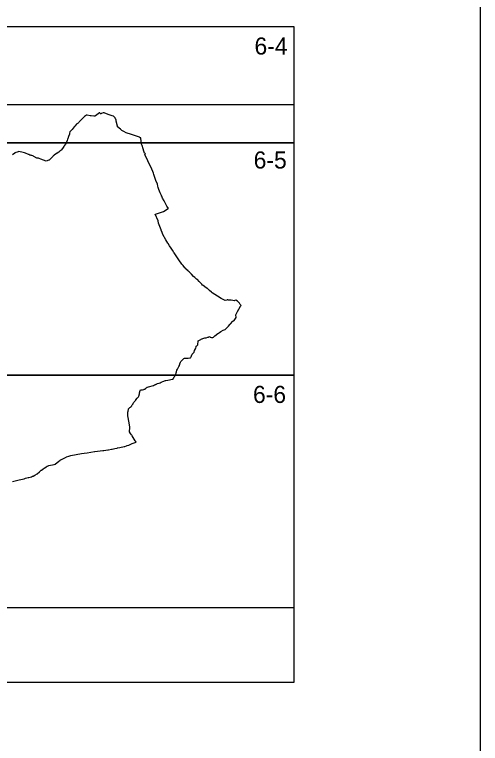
# Model space of a CAD drawing. Extents: x -447352 to -425530, y -1135906 to -1121091.
# Drawn here: x -439936.1 to -439685.5, y -1126663.9 to -1126271.9 of the extents above; entities that cross this region are included whole.
import ezdxf

# ---------------------------------------------------------------- set-up
doc = ezdxf.new("R2010")
doc.units = 0
for name, color, linetype in [('Vrstva 1', 7, 'Continuous'), ('Vrstva 10', 7, 'Continuous'), ('Vrstva 4', 7, 'Continuous')]:
    doc.layers.add(name, color=color, linetype=linetype)

msp = doc.modelspace()

# ---------------------------------------------------------------- linework, layer by layer
at = {"layer": 'Vrstva 1'}
msp.add_lwpolyline([(-441170.45, -1126016.81), (-441170.45, -1127066.81), (-439685.45, -1127066.81), (-439685.45, -1126016.81)], close=True, dxfattribs=at)
msp.add_lwpolyline([(-439937.16, -1126523.09), (-439933.62, -1126522.22), (-439930.85, -1126521.55), (-439930.18, -1126521.34), (-439928.69, -1126520.98), (-439928.48, -1126520.92), (-439927.05, -1126520.53), (-439926.45, -1126520.27), (-439926.23, -1126520.17), (-439926.07, -1126520.11), (-439925.25, -1126519.66), (-439925.19, -1126519.62), (-439923.88, -1126518.84), (-439922.73, -1126517.79), (-439922.08, -1126517.29), (-439921.95, -1126517.18), (-439921.93, -1126517.17), (-439921.77, -1126517.04), (-439921.62, -1126516.94), (-439920.82, -1126516.38), (-439920.76, -1126516.34), (-439920.69, -1126516.29), (-439920.18, -1126515.94), (-439919.81, -1126515.68), (-439919.15, -1126515.22), (-439918.56, -1126514.81), (-439918.4, -1126514.84), (-439918.39, -1126514.84), (-439918.37, -1126514.82), (-439917.64, -1126514.43), (-439914.68, -1126513.85), (-439914.26, -1126513.7), (-439912.23, -1126512.07), (-439911.76, -1126511.73), (-439911.73, -1126511.71), (-439911.37, -1126511.45), (-439911.19, -1126511.33), (-439909.8, -1126510.63), (-439908.39, -1126509.99), (-439908.09, -1126509.84), (-439906.83, -1126509.38), (-439905.83, -1126509.13), (-439900.12, -1126508.07), (-439898.7, -1126507.81), (-439896.99, -1126507.56), (-439893.12, -1126506.99), (-439892.88, -1126506.96), (-439888.58, -1126506.44), (-439888.05, -1126506.38), (-439885.9, -1126506.02), (-439885.58, -1126505.97), (-439883.92, -1126505.7), (-439883.52, -1126505.63), (-439882.11, -1126505.34), (-439880.82, -1126505.07), (-439880.61, -1126505.03), (-439879.44, -1126504.8), (-439878.77, -1126504.67), (-439878.75, -1126504.67), (-439877.84, -1126504.46), (-439877.77, -1126504.44), (-439877.12, -1126504.28), (-439876.77, -1126504.17), (-439875.88, -1126503.88), (-439875.44, -1126503.73), (-439874.79, -1126503.49), (-439874.67, -1126503.45), (-439873.58, -1126502.96), (-439873.58, -1126502.96), (-439873.46, -1126502.92), (-439872.81, -1126502.69), (-439872.72, -1126502.66), (-439872.29, -1126502.5), (-439870.63, -1126501.92), (-439870.65, -1126501.87), (-439870.76, -1126501.7), (-439870.92, -1126501.47), (-439871.14, -1126501.15), (-439872.84, -1126498.51), (-439873.05, -1126498.16), (-439873.22, -1126497.89), (-439873.66, -1126497.18), (-439874.19, -1126496.33), (-439874.03, -1126493.97), (-439874.02, -1126493.88), (-439874.41, -1126491.58), (-439874.41, -1126491.56), (-439874.42, -1126491.54), (-439874.42, -1126491.54), (-439874.42, -1126491.51), (-439874.83, -1126489.68), (-439874.84, -1126489.49), (-439874.9, -1126488.69), (-439875, -1126488.41), (-439875.01, -1126488.39), (-439875.12, -1126488.17), (-439875.16, -1126488.09), (-439875.17, -1126487.71), (-439875.2, -1126487.01), (-439875.15, -1126486.52), (-439875.15, -1126486.5), (-439875.06, -1126485.64), (-439875.04, -1126485.53), (-439874.75, -1126483.89), (-439874.67, -1126483.81), (-439874.37, -1126483.47), (-439874.31, -1126483.4), (-439874.05, -1126483.28), (-439873.99, -1126483.22), (-439873.73, -1126483.02), (-439873.5, -1126482.84), (-439873.29, -1126482.68), (-439873.23, -1126482.64), (-439873.15, -1126482.51), (-439873.07, -1126482.39), (-439872.96, -1126482.22), (-439872.74, -1126481.89), (-439872.32, -1126481.24), (-439872.19, -1126480.99), (-439872.18, -1126480.98), (-439872.04, -1126480.69), (-439871.99, -1126480.6), (-439871.81, -1126480.27), (-439871.67, -1126480.12), (-439871.37, -1126479.81), (-439871.2, -1126479.63), (-439870.92, -1126479.28), (-439870.79, -1126479.11), (-439870.1, -1126478.26), (-439869.44, -1126477.45), (-439869.15, -1126477.09), (-439868.91, -1126475.92), (-439868.85, -1126475.69), (-439868.78, -1126475.41), (-439868.46, -1126474.1), (-439868.38, -1126473.82), (-439868.38, -1126473.79), (-439868.36, -1126473.74), (-439868.2, -1126473.73), (-439868.18, -1126473.73), (-439867.94, -1126473.73), (-439867.25, -1126473.71), (-439867.24, -1126473.71), (-439867.21, -1126473.71), (-439866.53, -1126473.53), (-439866.33, -1126473.47), (-439865.91, -1126473.36), (-439865.89, -1126473.35), (-439865.83, -1126473.29), (-439865.53, -1126473.01), (-439865.41, -1126472.93), (-439865.07, -1126472.67), (-439864.65, -1126472.35), (-439864.58, -1126472.33), (-439864.02, -1126472.17), (-439861.32, -1126471.41), (-439860.73, -1126471.14), (-439860.4, -1126470.98), (-439860.35, -1126470.96), (-439860.25, -1126470.91), (-439859.89, -1126470.73), (-439859.84, -1126470.71), (-439859.81, -1126470.69), (-439859.8, -1126470.69), (-439859.77, -1126470.67), (-439859.46, -1126470.52), (-439859.4, -1126470.48), (-439859.29, -1126470.43), (-439858.21, -1126470.1), (-439857.78, -1126469.92), (-439857.26, -1126469.7), (-439856.25, -1126469.29), (-439854.83, -1126468.66), (-439854.69, -1126468.65), (-439853.56, -1126468.6), (-439851.16, -1126468.04), (-439850.63, -1126467.64), (-439850.56, -1126467.52), (-439850.47, -1126467.34), (-439850.21, -1126466.83), (-439849.86, -1126466.4), (-439849.84, -1126466.37), (-439849.63, -1126466.08), (-439849.52, -1126465.92), (-439849.51, -1126465.91), (-439848.97, -1126464.13), (-439848.96, -1126464.1), (-439848.76, -1126463.15), (-439848.5, -1126462.69), (-439848.31, -1126462.36), (-439847.76, -1126461.24), (-439847.38, -1126460.73), (-439847.35, -1126460.6), (-439847.28, -1126460.3), (-439847.25, -1126460.16), (-439847.19, -1126459.91), (-439847.17, -1126459.81), (-439846.85, -1126458.8), (-439846.84, -1126458.79), (-439846.55, -1126458.51), (-439845.89, -1126457.88), (-439845.84, -1126457.83), (-439845.37, -1126457.35), (-439845.11, -1126457.09), (-439845.01, -1126456.98), (-439844.64, -1126456.66), (-439844.6, -1126456.66), (-439844.59, -1126456.66), (-439844.18, -1126456.65), (-439844.01, -1126456.66), (-439843.38, -1126456.68), (-439842.67, -1126456.68), (-439841.7, -1126456.59), (-439841.67, -1126456.59), (-439841.42, -1126456.56), (-439841.2, -1126456.2), (-439841.15, -1126456.07), (-439841.13, -1126456.02), (-439841.11, -1126455.96), (-439840.75, -1126454.94), (-439840.61, -1126454.77), (-439840.51, -1126454.66), (-439840.47, -1126454.62), (-439840.41, -1126454.54), (-439840.29, -1126454.41), (-439840.02, -1126454.09), (-439839.93, -1126453.99), (-439839.83, -1126453.87), (-439839.49, -1126453.48), (-439839.42, -1126453.09), (-439839.36, -1126452.78), (-439839.29, -1126452.65), (-439838.74, -1126451.73), (-439838.63, -1126451.34), (-439838.44, -1126450.64), (-439838.32, -1126450.35), (-439838.03, -1126450.08), (-439837.48, -1126449.57), (-439837.41, -1126449.51), (-439837.31, -1126447.4), (-439836.29, -1126446.91), (-439835.89, -1126446.7), (-439835.64, -1126446.57), (-439835.35, -1126446.41), (-439835.13, -1126446.33), (-439834.79, -1126446.2), (-439834.74, -1126446.19), (-439833.65, -1126445.78), (-439833.64, -1126445.78), (-439833.15, -1126445.72), (-439833.07, -1126445.7), (-439832.04, -1126445.44), (-439831.89, -1126445.4), (-439831.8, -1126445.37), (-439831.63, -1126445.32), (-439831.1, -1126445.15), (-439831.1, -1126445.15), (-439831.09, -1126445.16), (-439831.09, -1126445.16), (-439831.06, -1126445.22), (-439830.93, -1126445.44), (-439830.05, -1126445.54), (-439829.85, -1126445.56), (-439829.49, -1126445.6), (-439829.4, -1126445.56), (-439828.97, -1126445.38), (-439828.32, -1126444.67), (-439826.68, -1126443.51), (-439826.59, -1126443.44), (-439826.42, -1126443.33), (-439825.91, -1126442.91), (-439825.16, -1126442.31), (-439823.89, -1126441.74), (-439823.27, -1126441.47), (-439822.73, -1126441.23), (-439822.67, -1126441.2), (-439821.02, -1126439.53), (-439820.18, -1126438.64), (-439819.82, -1126438.26), (-439818.63, -1126436.9), (-439818.03, -1126436.44), (-439817.98, -1126436.4), (-439817.14, -1126435.39), (-439816.94, -1126434.82), (-439817.03, -1126433.49), (-439816.81, -1126433), (-439816.17, -1126431.55), (-439814.71, -1126429.07), (-439814.68, -1126429.02), (-439814.68, -1126429.02), (-439814.66, -1126428.99), (-439814.63, -1126428.95), (-439814.48, -1126428.76), (-439814.22, -1126428.42), (-439814.48, -1126428.12), (-439814.62, -1126427.9), (-439815.09, -1126427.16), (-439815.29, -1126426.97), (-439815.44, -1126426.81), (-439815.63, -1126426.61), (-439816.21, -1126426.04), (-439817.06, -1126425.57), (-439817.51, -1126425.75), (-439817.84, -1126425.87), (-439819.59, -1126425.6), (-439820.2, -1126425.51), (-439820.34, -1126425.5), (-439820.93, -1126425.48), (-439821.31, -1126425.43), (-439821.47, -1126425.4), (-439821.51, -1126425.4), (-439821.54, -1126425.39), (-439821.54, -1126425.39), (-439821.57, -1126425.4), (-439821.67, -1126425.43), (-439821.8, -1126425.46), (-439822.7, -1126425.7), (-439822.77, -1126425.67), (-439824.84, -1126424.63), (-439826.86, -1126423.35), (-439829.77, -1126421.53), (-439829.93, -1126421.39), (-439829.97, -1126421.36), (-439830.06, -1126421.28), (-439831.2, -1126420.35), (-439832.35, -1126419.3), (-439832.46, -1126419.2), (-439833.67, -1126418.44), (-439833.95, -1126418.21), (-439834.58, -1126417.71), (-439834.89, -1126417.47), (-439835.39, -1126416.94), (-439836.11, -1126416.18), (-439836.26, -1126416.02), (-439836.72, -1126415.53), (-439837.69, -1126414.5), (-439837.89, -1126414.39), (-439837.89, -1126414.39), (-439838.07, -1126414.3), (-439838.27, -1126414.2), (-439839.1, -1126413.37), (-439839.73, -1126412.74), (-439840.91, -1126411.57), (-439841.84, -1126410.63), (-439842, -1126410.48), (-439842.44, -1126410.03), (-439842.68, -1126409.79), (-439842.77, -1126409.7), (-439842.81, -1126409.66), (-439843.33, -1126409.14), (-439843.97, -1126408.49), (-439844.05, -1126408.41), (-439844.07, -1126408.39), (-439844.22, -1126408.24), (-439845.05, -1126407.4), (-439845.43, -1126406.9), (-439845.71, -1126406.53), (-439846.03, -1126406.1), (-439846.39, -1126405.62), (-439847.34, -1126404.36), (-439847.71, -1126403.82), (-439850.25, -1126400.08), (-439850.42, -1126399.82), (-439851.19, -1126398.63), (-439851.86, -1126397.62), (-439852.7, -1126396.29), (-439853.5, -1126395.02), (-439853.58, -1126394.89), (-439854.67, -1126393.04), (-439856.35, -1126390.19), (-439856.35, -1126390.18), (-439856.35, -1126390.18), (-439856.36, -1126390.18), (-439856.69, -1126389.2), (-439857.14, -1126387.9), (-439857.2, -1126387.7), (-439858.58, -1126384.19), (-439858.87, -1126382.94), (-439860.35, -1126379.26), (-439859.72, -1126379.06), (-439856, -1126377.82), (-439854.03, -1126376.6), (-439853.85, -1126376.49), (-439853.79, -1126376.45), (-439853.59, -1126376.33), (-439853.32, -1126376.16), (-439854.24, -1126374.97), (-439855.65, -1126372.19), (-439856.4, -1126370.72), (-439856.93, -1126369.56), (-439856.95, -1126369.52), (-439857.01, -1126369.39), (-439857.02, -1126369.36), (-439857.04, -1126369.33), (-439857.08, -1126369.24), (-439857.41, -1126368.51), (-439857.73, -1126367.72), (-439858.44, -1126365.95), (-439858.85, -1126364.91), (-439859, -1126364.28), (-439859.26, -1126363.15), (-439860, -1126361.26), (-439860.2, -1126360.66), (-439861.14, -1126358.03), (-439861.41, -1126357.31), (-439862.6, -1126354.22), (-439862.67, -1126354.04), (-439862.7, -1126353.96), (-439866.05, -1126347.15), (-439865.74, -1126347.01), (-439865.72, -1126347), (-439865.82, -1126346.83), (-439865.9, -1126346.73), (-439866.07, -1126346.5), (-439866.13, -1126346.42), (-439866.74, -1126344.94), (-439866.79, -1126344.65), (-439866.89, -1126344.19), (-439866.9, -1126344.13), (-439867.41, -1126342.29), (-439867.71, -1126341.66), (-439867.72, -1126341.58), (-439867.76, -1126341.22), (-439867.9, -1126340.13), (-439868.18, -1126338.29), (-439868.24, -1126338.27), (-439868.54, -1126338.17), (-439868.92, -1126337.91), (-439868.93, -1126337.91), (-439873.23, -1126336.5), (-439876.02, -1126335.52), (-439877.33, -1126334.9), (-439878.3, -1126334.34), (-439879.02, -1126333.56), (-439880.7, -1126332.29), (-439880.76, -1126331.99), (-439881.34, -1126329.29), (-439881.49, -1126328.75), (-439881.67, -1126328.24), (-439881.72, -1126328.08), (-439881.97, -1126327.56), (-439882.22, -1126327.25), (-439882.8, -1126326.56), (-439883.55, -1126326.35), (-439885.73, -1126325.69), (-439887.82, -1126324.73), (-439888.44, -1126324.73), (-439889.39, -1126325.1), (-439889.52, -1126325.19), (-439889.59, -1126325.24), (-439889.73, -1126325.34), (-439889.77, -1126325.37), (-439889.79, -1126325.35), (-439890, -1126325.1), (-439890.25, -1126324.82), (-439890.33, -1126324.72), (-439890.42, -1126324.76), (-439890.93, -1126325.15), (-439891.12, -1126325.3), (-439891.79, -1126325.82), (-439892.54, -1126326.38), (-439892.88, -1126326.6), (-439893.47, -1126326.56), (-439894.95, -1126326.41), (-439895.41, -1126326.32), (-439897, -1126326), (-439897.3, -1126326.11), (-439897.86, -1126326.46), (-439898.41, -1126326.78), (-439898.9, -1126327.24), (-439899.43, -1126327.73), (-439899.83, -1126328.12), (-439899.84, -1126328.13), (-439900.17, -1126328.47), (-439900.3, -1126328.61), (-439900.81, -1126329.16), (-439901.26, -1126329.71), (-439901.42, -1126329.9), (-439901.78, -1126330.33), (-439902.52, -1126330.66), (-439902.54, -1126330.66), (-439902.74, -1126330.91), (-439903.6, -1126331.93), (-439903.98, -1126332.38), (-439905.11, -1126333.74), (-439905.12, -1126333.75), (-439906.36, -1126334.92), (-439906.48, -1126335.76), (-439906.53, -1126336.13), (-439906.57, -1126336.23), (-439907.05, -1126337.58), (-439907.49, -1126338.82), (-439907.52, -1126338.9), (-439907.82, -1126339.59), (-439908.75, -1126341.77), (-439908.77, -1126341.78), (-439909.34, -1126342.46), (-439909.64, -1126342.81), (-439909.64, -1126342.82), (-439909.98, -1126343.36), (-439910.85, -1126344.75), (-439910.94, -1126344.89), (-439911.11, -1126345.02), (-439911.64, -1126345.41), (-439912.25, -1126345.86), (-439912.25, -1126345.86), (-439913.22, -1126346.49), (-439913.35, -1126346.58), (-439913.53, -1126346.7), (-439914.83, -1126347.56), (-439914.84, -1126347.57), (-439915.1, -1126347.83), (-439915.22, -1126347.95), (-439915.44, -1126348.18), (-439915.72, -1126348.46), (-439916.29, -1126349.03), (-439917.45, -1126350.19), (-439917.65, -1126350.27), (-439919.15, -1126350.84), (-439921.96, -1126349.72), (-439921.96, -1126349.73), (-439921.97, -1126349.75), (-439922.88, -1126349.37), (-439923.19, -1126349.24), (-439923.21, -1126349.24), (-439923.6, -1126349.24), (-439924.08, -1126349.24), (-439925.64, -1126348.25), (-439925.9, -1126348.12), (-439926.19, -1126347.96), (-439926.25, -1126347.93), (-439926.29, -1126347.91), (-439926.83, -1126347.68), (-439926.88, -1126347.68), (-439926.89, -1126347.68), (-439927.04, -1126347.67), (-439927.16, -1126347.66), (-439927.47, -1126347.64), (-439927.49, -1126347.64), (-439927.49, -1126347.64), (-439927.6, -1126347.6), (-439927.84, -1126347.5), (-439928.44, -1126347.25), (-439928.6, -1126347.18), (-439930.12, -1126346.45), (-439930.74, -1126346.27), (-439931.41, -1126346.07), (-439933.73, -1126345.64), (-439933.74, -1126345.64), (-439934.14, -1126345.75), (-439935.88, -1126346.33), (-439936.01, -1126346.44), (-439937.22, -1126347.4)], dxfattribs=at)
at = {"layer": 'Vrstva 10'}
msp.add_lwpolyline([(-439785.86, -1126320.23), (-439785.86, -1126631.21), (-440118.73, -1126631.21), (-440118.73, -1126465.91), (-440098.36, -1126465.91), (-440098.36, -1126340.91), (-440098.36, -1126320.23), (-439785.86, -1126320.23)], dxfattribs=at)
at = {"layer": 'Vrstva 4'}
msp.add_line((-440098.36, -1126278.41), (-439785.86, -1126278.41), dxfattribs=at)
msp.add_lwpolyline([(-439785.86, -1126278.41), (-439785.86, -1126340.91), (-439942.11, -1126340.91), (-439942.11, -1126278.41)], dxfattribs=at)
for points in [[(-439785.86, -1126340.91), (-439785.86, -1126465.91), (-439942.11, -1126465.91), (-439942.11, -1126340.91)], [(-439785.86, -1126465.91), (-439785.86, -1126590.91), (-439942.11, -1126590.91), (-439942.11, -1126465.91)]]:
    msp.add_lwpolyline(points, close=True, dxfattribs=at)

# ---------------------------------------------------------------- texts
at = {"layer": 'Vrstva 1'}
for s, p in [('6-4', (-439806.99, -1126293.46)), ('6-5', (-439807.44, -1126354.75)), ('6-6', (-439807.81, -1126480.82))]:
    msp.add_text(s, height=9.2, dxfattribs=at).set_placement(p)

doc.saveas('drawing.dxf')
